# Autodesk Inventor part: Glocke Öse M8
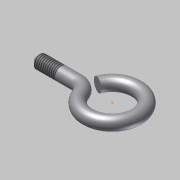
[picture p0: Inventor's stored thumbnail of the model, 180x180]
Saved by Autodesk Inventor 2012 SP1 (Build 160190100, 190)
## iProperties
Created: 2012-04
Part Number: Glocke Öse M8
Document SubType Name: Modeling
Designer: Kuehlem
Density: 1 g/cm^3
Material: Standard
Author: Kuehlem
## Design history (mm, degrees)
sketch "Skizze1"
  geometry: L1 (-44.307, 0)-(41.292, 0) reference; L2 (0, -21)-(0, 21) reference; L3 (-32.079, 0)-(-7.5, 0); L4 (29.063, 0)-(29.063, 0); L5 (29.063, 0)-(29.063, 0); A1 r 8 centre (-7.5, -8) between (0, -5.217) and (-7.5, 0); A2 r 15 centre (14.063, 0) between (0, -5.217) and (0, 5.217); A3 r 15 centre (14.063, 0) between (0, -5.217) and (0, 5.217); 1 further point
  constraints: 8 point on circle, 6 end point, 6 point on line, 3 centre point, 3 tangent, 2 symmetric about line, 1 perpendicular, 1 other
  dimensions: "d10" = 8 radius of A1; "d12" = 15 radius of A2
workplane "Arbeitsebene1"
sketch "Skizze2"
  geometry: C1 r 4 at (0, 0); 1 further point
  constraints: 1 centre point, 1 coincident
  dimensions: "d2" = 8 diameter of C1
feature "Sweeping1" sketch "Skizze2" dims "d3" = 0
feature "Gewinde1" dims "d5" = 15, "d6" = 0
chamfer "Fase1" distance "d7" = 2; stored, may be unused: second distance "d8" = 2, angle "d9" = 45 deg
workpoint "Arbeitspunkt1"
node "Volumenkörper1"
